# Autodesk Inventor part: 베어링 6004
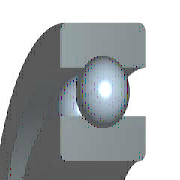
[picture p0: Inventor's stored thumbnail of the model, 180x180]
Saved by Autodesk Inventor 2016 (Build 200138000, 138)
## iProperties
Created: 2012-02
Part Number: 베어링 6004
Material: 강철, 연강
Description: 깊은 그루브 볼 베어링
Document SubType Name: Modeling
Standard: KS B 2023
Designer: mduedu
Standards Organization: KS
Language: ko-KR
Size Designation: 6004 - 20 x 42 x 12
Categories: <MemberInstance><Categories><Category DisplayName="샤프트 부품" InternalName="7f7aeb1f-a693-4053-b835-cee3144e0d98" Mnemonic="SHFT"><Category DisplayName="베어링" Inter
Density: 7.85 g/cm^3
Appearance: 노란색
Mass: 68.2267 g
Surface Area: 70.0178 cm^2
Volume: 8.6913 cm^3
IsCustomPart: 1
Author: mduedu
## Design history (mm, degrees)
sketch "스케치" dims "d0" = 5.72 (= -0.26 x WD + 0.26 x BD)
  geometry: L1 (3.14, 15.5)-(8.86, 15.5); L2 (6, 15.5)-(6, 12.64); L3 (6, 15.5)-(6, 18.36); L4 (3.875, 13.586)-(0, 13.586); L5 (0, 10)-(12, 10); L6 (3.875, 17.414)-(0, 17.414); L7 (0, 21)-(12, 21); L8 (12, 10)-(12, 13.586); L9 (8.125, 13.586)-(12, 13.586); L10 (8.125, 17.414)-(12, 17.414); L11 (12, 21)-(12, 17.414); L12 (-1.4, 0)-(8.4, 0) reference; L13 (0, -0.3)-(0, 5.3) reference
  constraints: 22 end point, 4 point on line, 2 collinear, 2 perpendicular, 2 symmetric about line, 1 midpoint, 1 parallel, 14 other
  dimensions: "d9" = 20 diameter of L5 L12 (= WD); "d11" = 42 diameter of L7 L12 (= BD); "d12" = 12 distance between parallel lines of L8 L13 (= KB); "d13" = 27.172 diameter of L9 L12 (= 0.326 x BD + 0.674 x WD)
revolve "본체" stored, may be unused: angle "d6" = 90 deg
revolve "볼" stored, may be unused: angle "d7" = 90 deg
pattern_circular "IDS_ARRAYBALL[SIMPL:T]" dims angle "d3" = 360 deg
body "Solid1"
fillet "모깎기1" dims "d1" = 0.6 (= KRS)
other parameters: "WD" = 20 [user parameter; used in 5 equation terms], "BD" = 42 [user parameter; used in 5 equation terms], "KB" = 12 [user parameter; used in 1 equation term], "KRS" = 0.6 [user parameter; used in 1 equation term], "d4" = 0, "d5" = 0, "d8" = 0, "d14" = 0, "d15" = 0, "BBA" = 0 [user parameter], "BC0" = 5000000 [user parameter], "BC" = 9360000 [user parameter], "BR" = 21 (= 0.5 x BD) [user parameter]
